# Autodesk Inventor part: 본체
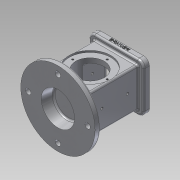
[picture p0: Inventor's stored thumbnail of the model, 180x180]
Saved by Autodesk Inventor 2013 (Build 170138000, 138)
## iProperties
Created: 2018-10
Part Number: 본체
Material: 알루미늄 6061
Document SubType Name: Modeling
Designer: Administrator
Mass: 987.13 g
Surface Area: 747.264 cm^2
Volume: 364.255 cm^3
Density: 2.71 g/cm^3
Author: Administrator
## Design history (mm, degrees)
sketch "스케치1"
  geometry: L1 (37, -33)-(-37, -33); L2 (-37, -33)-(-37, 33); L3 (-37, 33)-(37, 33); L4 (37, 33)-(37, -33); L5 (37, -33)-(-37, 33); L6 (-37, -33)-(37, 33); 1 further point
  constraints: 12 end point, 2 midpoint, 2 parallel, 1 horizontal, 1 perpendicular
  dimensions: "d0" = 74 distance of L2.end L3.end; "d2" = 66 distance of L1.end L2.end
extrude "돌출1" new body sketch "스케치1" distance "d3" = 108; taper "d4" = 0 deg
sketch "스케치2"
  geometry: L1 (-37, -33)-(37, -33) reference; L2 (37, -33)-(37, 33) reference; L3 (37, 33)-(-37, 33) reference; L4 (-37, 33)-(-37, -33) reference; C1 r 62.5 at (0, 0); 1 further point
  constraints: 1 centre point, 1 coincident
  dimensions: "d5" = 125 diameter of C1
extrude "돌출2" join sketch "스케치2" distance "d6" = 10; taper "d7" = 0 deg
sketch "스케치3"
  geometry: L1 (37, 33)-(-37, 33) reference; L2 (-37, 33)-(-37, -33) reference; L3 (-37, -33)-(37, -33) reference; L4 (37, -33)-(37, 33) reference; L5 (-46, 41)-(46, 41); L6 (46, 41)-(46, -41); L7 (46, -41)-(-46, -41); L8 (-46, -41)-(-46, 41); L9 (-46, 41)-(46, -41); L10 (46, 41)-(-46, -41); 1 further point
  constraints: 12 end point, 2 midpoint, 2 parallel, 1 horizontal, 1 perpendicular
  dimensions: "d8" = 92 distance of L5.start L5.end; "d11" = 82 distance of L7.end L5.start
extrude "돌출3" join sketch "스케치3" distance "d12" = 10; taper "d13" = 0 deg
sketch "스케치5"
  geometry: L1 (99.5, -10)-(-25.5, -10) reference; C1 r 35 at (37, 44); 1 further point
  constraints: 1 centre point, 1 vertical alignment
  dimensions: "d14" = 70 diameter of C1; "d16" = 54 distance from line of L1 C1.centre
extrude "돌출4" cut sketch "스케치5" distance "d17" = 3; taper "d18" = 0 deg
sketch "스케치6"
  geometry: L1 (99.5, -10)-(-25.5, -10) reference; C1 r 35 at (37, 44); 1 further point
  constraints: 1 centre point, 1 vertical alignment
  dimensions: "d19" = 70 diameter of C1; "d20" = 54 distance from line of L1 C1.centre
extrude "돌출5" cut sketch "스케치6" distance "d21" = 3; taper "d22" = 0 deg
sketch "스케치7"
  geometry: C1 r 35 at (0, 0) reference; C2 r 24 at (0, 0); 1 further point
  constraints: 1 centre point, 1 coincident
  dimensions: "d23" = 48 diameter of C2
extrude "돌출6" cut sketch "스케치7" stored distance "d24" = 3; taper "d25" = 0 deg
sketch "스케치8"
  geometry: C1 r 62.5 at (0, 0) reference; C2 r 28 at (0, 0)
  constraints: 1 centre point, 1 coincident
  dimensions: "d26" = 56 diameter of C2
extrude "돌출7" cut sketch "스케치8" distance "d27" = 18; taper "d28" = -10 deg
sketch "스케치10"
  geometry: L1 (-26, 26)-(26, 26); L2 (26, 26)-(26, -26); L3 (26, -26)-(-26, -26); L4 (-26, -26)-(-26, 26); L5 (-26, 26)-(26, -26); L6 (26, 26)-(-26, -26); 1 further point
  constraints: 12 end point, 2 midpoint, 2 parallel, 1 horizontal, 1 perpendicular
  dimensions: "d29" = 52 distance of L2.end L3.end; "d31" = 52 distance of L1.end L2.end
extrude "돌출8" cut sketch "스케치10" distance "d32" = 8; taper "d33" = 0 deg
sketch "스케치11"
  geometry: L1 (-22, 22)-(22, 22); L2 (22, 22)-(22, -22); L3 (22, -22)-(-22, -22); L4 (-22, -22)-(-22, 22); L5 (-22, 22)-(22, -22); L6 (22, 22)-(-22, -22); 1 further point
  constraints: 12 end point, 2 midpoint, 2 parallel, 1 horizontal, 1 perpendicular
  dimensions: "d34" = 44 distance of L1.start L1.end; "d36" = 44 distance of L1.end L2.end
extrude "돌출9" cut sketch "스케치11" distance "d37" = 74; taper "d38" = 0 deg
sketch "스케치12"
  geometry: C1 r 24 at (0, 0) reference; 2 further points
  constraints: 1 vertical alignment
  dimensions: "d39" = 29 distance of C1.centre point (0, 29)
hole "구멍1" sketch "스케치12" at (0, 29) diameter "d40" = 3.242; stored, may be unused: countersink angle "d44" = 90 deg, drill point angle "d46" = 118 deg; dims "d41" = 4, "d42" = 4, "d43" = 2, "d45" = 6
sketch "스케치13"
  geometry: L1 (-36, 31)-(36, 31); L2 (36, 31)-(36, -31); L3 (36, -31)-(-36, -31); L4 (-36, -31)-(-36, 31); L5 (-36, 31)-(36, -31); L6 (36, 31)-(-36, -31); 5 further points
  constraints: 12 end point, 4 coincident, 2 midpoint, 2 parallel, 1 horizontal, 1 perpendicular
  dimensions: "d50" = 72 distance of L1.start L1.end; "d52" = 62 distance of L1.end L2.end
hole "구멍2" sketch "스케치13" at (-36, 31), (36, 31), (36, -31), (-36, -31) diameter "d53" = 3.242; stored, may be unused: countersink angle "d57" = 90 deg, drill point angle "d59" = 118 deg; dims "d54" = 4, "d55" = 4, "d56" = 2, "d58" = 6
fillet "모깎기1" dims "d60" = 10
sketch "스케치14"
  geometry: C1 r 62.5 at (0, 0) reference; C2 r 4.5 at (0, 50)
  constraints: 1 centre point, 1 vertical alignment
  dimensions: "d61" = 9 diameter of C2; "d62" = 50 distance of C1.centre C2.centre
extrude "돌출10" cut sketch "스케치14" stored distance "d63" = 74; taper "d64" = 0 deg
sketch "스케치15"
  geometry: 3 further points
  constraints: 2 vertical alignment
  dimensions: "d68" = 37 distance of point (33, -10) point (33, 27); "d69" = 43 distance of point (33, 27) point (33, 70)
hole "구멍3" sketch "스케치15" at (33, 70), (33, 27) diameter "d70" = 4.134; stored, may be unused: countersink angle "d74" = 90 deg, drill point angle "d76" = 118 deg; dims "d71" = 4, "d72" = 4, "d73" = 2, "d75" = 30
sketch "스케치16"
  geometry: 3 further points
  constraints: 2 vertical alignment
  dimensions: "d77" = 37 distance of point (33, -10) point (33, 27); "d78" = 43 distance of point (33, 27) point (33, 70)
hole "구멍4" sketch "스케치16" at (33, 70), (33, 27) diameter "d79" = 4.134; stored, may be unused: countersink angle "d83" = 90 deg, drill point angle "d85" = 118 deg; dims "d80" = 4, "d81" = 4, "d82" = 2, "d84" = 30
fillet "모깎기2" dims "d86" = 3
fillet "모깎기3" dims "d87" = 3
chamfer "모따기1" distance "d88" = 1; stored, may be unused: second distance "d89" = 2, angle "d90" = 45 deg
sketch "스케치17"
  geometry: L1 (72, 0)-(0, 0) reference; L2 (-10, 0)-(-10, -7) reference; 2 further points
  constraints: 1 other
  dimensions: "d91" = 46 distance from line of point (36, -4) L2; "d92" = 4 distance from line of point (36, -4) L1
feature "엠보싱1" sketch "스케치17" dims "d0" = 74, "d2" = 66, "d93" = 0.5, "d94" = 0
node "솔리드1"
pattern_circular "원형 패턴1" dims angle "d48" = 360 deg
mirror "대칭1"
pattern_circular "원형 패턴2" dims angle "d66" = 360 deg
